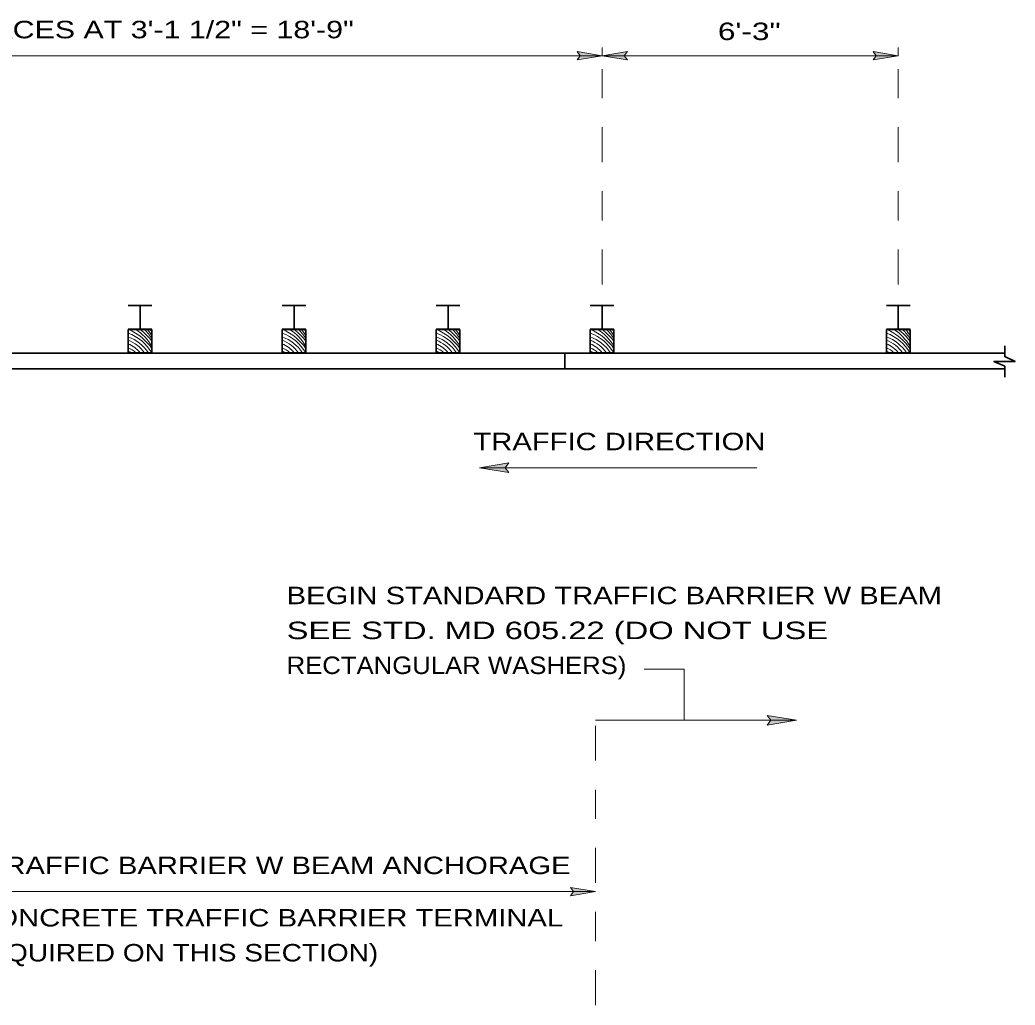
# Model space of a CAD drawing. Extents: x 49.7 to 60, y 209.2 to 216.1.
# Drawn here: x 56.086 to 59.505, y 212.714 to 216.099 of the extents above; entities that cross this region are included whole.
import ezdxf
from ezdxf.enums import TextEntityAlignment as Align

# ---------------------------------------------------------------- set-up
doc = ezdxf.new("R2010")
doc.units = 0
doc.header["$LTSCALE"] = 0.024
doc.linetypes.add('DOT_DASHED', pattern=[7.7, 5, -1.2, 0.3, -1.2])
for name, color, linetype, lineweight in [('1', 7, 'Continuous', 35), ('10', 7, 'Continuous', 13), ('12', 7, 'Continuous', 53), ('6', 7, 'Continuous', 13)]:
    doc.layers.add(name, color=color, linetype=linetype, lineweight=lineweight)

msp = doc.modelspace()

# ---------------------------------------------------------------- hatches: boundary and pattern name
at = {"layer": '10'}
for points in [[(58.08642, 215.97608), (58, 215.9905), (58.01075, 215.97608), (58, 215.96175)], [(58.08642, 215.97608), (58.17283, 215.9905), (58.162, 215.97608), (58.17283, 215.96175)], [(59.10375, 215.97608), (59.01733, 215.9905), (59.02817, 215.97608), (59.01733, 215.96175)], [(57.76608, 214.54375), (57.66525, 214.56058), (57.76608, 214.57733), (57.7535, 214.56058)], [(58.7545, 213.6925), (58.65367, 213.67567), (58.66625, 213.6925), (58.65367, 213.70925)], [(58.06392, 213.10408), (57.9775, 213.08967), (57.98833, 213.10408), (57.9775, 213.11842)]]:
    msp.add_hatch(color=256, dxfattribs=at).paths.add_polyline_path(points)

# ---------------------------------------------------------------- linework, layer by layer
at = {"layer": '1'}
for p, q in [((56.458, 215.11825), (56.5395, 215.11825)), ((56.49867, 215.03692), (56.49867, 215.11825)), ((56.98717, 215.11825), (57.06867, 215.11825)), ((57.02783, 215.03692), (57.02783, 215.11825)), ((57.51633, 215.11825), (57.59775, 215.11825)), ((57.557, 215.03692), (57.557, 215.11825)), ((58.0455, 215.11825), (58.12692, 215.11825)), ((58.08617, 215.03692), (58.08617, 215.11825)), ((59.063, 215.11825), (59.14442, 215.11825)), ((59.10375, 215.03692), (59.10375, 215.11825)), ((56.458, 215.03692), (56.53933, 215.03692)), ((56.458, 215.03558), (56.458, 214.9555)), ((56.458, 215.03558), (56.53933, 215.03558)), ((56.53933, 215.03558), (56.53933, 214.9555)), ((56.98717, 215.03692), (57.0685, 215.03692)), ((56.98717, 215.03558), (56.98717, 214.9555)), ((56.98717, 215.03558), (57.0685, 215.03558)), ((57.0685, 215.03558), (57.0685, 214.9555)), ((57.51633, 215.03692), (57.59767, 215.03692)), ((57.51633, 215.03558), (57.51633, 214.9555)), ((57.51633, 215.03558), (57.59767, 215.03558)), ((57.59767, 215.03558), (57.59767, 214.9555)), ((58.0455, 215.03692), (58.12683, 215.03692)), ((58.0455, 215.03558), (58.0455, 214.9555)), ((58.0455, 215.03558), (58.12683, 215.03558)), ((58.12683, 215.03558), (58.12683, 214.9555)), ((59.063, 215.03692), (59.14442, 215.03692)), ((59.063, 215.03558), (59.063, 214.9555)), ((59.063, 215.03558), (59.14442, 215.03558)), ((59.14442, 215.03558), (59.14442, 214.9555)), ((53.85392, 214.954), (59.47, 214.954)), ((56.458, 214.9555), (56.53933, 214.9555)), ((56.98717, 214.9555), (57.0685, 214.9555)), ((57.51633, 214.9555), (57.59767, 214.9555)), ((57.95833, 214.90025), (57.95833, 214.95458)), ((58.0455, 214.9555), (58.12683, 214.9555)), ((59.063, 214.9555), (59.14442, 214.9555)), ((59.47, 214.89975), (53.72958, 214.89975))]:
    msp.add_line(p, q, dxfattribs=at)
at = {"layer": '10'}
for p, q in [((58, 215.9905), (58.08642, 215.97608)), ((58, 215.9905), (58.01075, 215.97608)), ((58.08642, 215.97608), (58.08642, 216.00492)), ((58.17283, 215.9905), (58.08642, 215.97608)), ((58.17283, 215.9905), (58.162, 215.97608)), ((59.01733, 215.9905), (59.10375, 215.97608)), ((59.01733, 215.9905), (59.02817, 215.97608)), ((59.10375, 215.97608), (59.10375, 216.00492)), ((58.08642, 215.97608), (54.9095, 215.97608)), ((58, 215.96175), (58.08642, 215.97608)), ((58, 215.96175), (58.01075, 215.97608)), ((58.08642, 215.97608), (59.10375, 215.97608)), ((58.17283, 215.96175), (58.08642, 215.97608)), ((58.17283, 215.96175), (58.162, 215.97608)), ((59.01733, 215.96175), (59.10375, 215.97608)), ((59.01733, 215.96175), (59.02817, 215.97608)), ((57.76608, 214.57733), (57.66525, 214.56058)), ((57.66525, 214.56058), (58.61758, 214.56058)), ((57.76608, 214.54375), (57.66525, 214.56058)), ((57.76608, 214.57733), (57.7535, 214.56058)), ((57.76608, 214.54375), (57.7535, 214.56058)), ((58.23025, 213.86825), (58.36817, 213.86825)), ((58.36817, 213.86825), (58.36817, 213.6925)), ((58.65367, 213.70925), (58.7545, 213.6925)), ((58.65367, 213.70925), (58.66625, 213.6925)), ((58.06392, 213.6925), (58.7545, 213.6925)), ((58.65367, 213.67567), (58.7545, 213.6925)), ((58.65367, 213.67567), (58.66625, 213.6925)), ((57.9775, 213.11842), (58.06392, 213.10408)), ((57.9775, 213.11842), (57.98833, 213.10408)), ((53.60783, 213.10408), (58.06392, 213.10408)), ((57.9775, 213.08967), (58.06392, 213.10408)), ((57.9775, 213.08967), (57.98833, 213.10408))]:
    msp.add_line(p, q, dxfattribs=at)
at = {"layer": '10', "linetype": 'DOT_DASHED'}
for p, q in [((58.08642, 215.19025), (58.08642, 216.00492)), ((59.10375, 215.19025), (59.10375, 216.00492)), ((58.06392, 212.71392), (58.06392, 213.72125))]:
    msp.add_line(p, q, dxfattribs=at)
at = {"layer": '10', "lineweight": 35}
for p, q in [((59.47, 214.942), (59.47, 214.97975)), ((59.47, 214.90883), (59.47, 214.87117))]:
    msp.add_line(p, q, dxfattribs=at)
at = {"layer": '10'}
for points in [[(58.08642, 215.97608), (58, 215.9905), (58.01075, 215.97608), (58, 215.96175)], [(58.08642, 215.97608), (58.17283, 215.9905), (58.162, 215.97608), (58.17283, 215.96175)], [(59.10375, 215.97608), (59.01733, 215.9905), (59.02817, 215.97608), (59.01733, 215.96175)], [(57.76608, 214.54375), (57.66525, 214.56058), (57.76608, 214.57733), (57.7535, 214.56058)], [(58.7545, 213.6925), (58.65367, 213.67567), (58.66625, 213.6925), (58.65367, 213.70925)], [(58.06392, 213.10408), (57.9775, 213.08967), (57.98833, 213.10408), (57.9775, 213.11842)]]:
    msp.add_lwpolyline(points, close=True, dxfattribs=at)
at = {"layer": '10', "lineweight": 35}
msp.add_lwpolyline([(59.46958, 214.90892), (59.43242, 214.92517), (59.505, 214.92575), (59.46958, 214.94258)], dxfattribs=at)
at = {"layer": '6'}
for centre, radius, start, end in [((56.38367, 214.86339), 0.18836, 34.17863, 66.11666), ((56.37975, 214.87918), 0.18798, 31.80949, 56.32878), ((56.38588, 214.8853), 0.18798, 35.19443, 53.09813), ((56.38168, 214.90169), 0.18798, 32.90846, 45.43912), ((56.38168, 214.91219), 0.18798, 32.90846, 41.04364), ((56.37706, 214.93151), 0.18798, 30.21852, 33.63016), ((56.91279, 214.86339), 0.18836, 34.17863, 66.11666), ((56.90887, 214.87918), 0.18798, 31.80949, 56.32878), ((56.915, 214.8853), 0.18798, 35.19443, 53.09813), ((56.9108, 214.90169), 0.18798, 32.90846, 45.43912), ((56.9108, 214.91219), 0.18798, 32.90846, 41.04364), ((56.90618, 214.93151), 0.18798, 30.21852, 33.63016), ((57.44192, 214.86339), 0.18836, 34.17863, 66.11666), ((57.438, 214.87918), 0.18798, 31.80949, 56.32878), ((57.44413, 214.8853), 0.18798, 35.19443, 53.09813), ((57.43993, 214.90169), 0.18798, 32.90846, 45.43912), ((57.43993, 214.91219), 0.18798, 32.90846, 41.04364), ((57.43531, 214.93151), 0.18798, 30.21852, 33.63016), ((57.97104, 214.86339), 0.18836, 34.17863, 66.11666), ((57.96712, 214.87918), 0.18798, 31.80949, 56.32878), ((57.97325, 214.8853), 0.18798, 35.19443, 53.09813), ((57.96905, 214.90169), 0.18798, 32.90846, 45.43912), ((57.96905, 214.91219), 0.18798, 32.90846, 41.04364), ((57.96443, 214.93151), 0.18798, 30.21852, 33.63016), ((58.98859, 214.86335), 0.18836, 34.17863, 66.11666), ((58.98467, 214.87914), 0.18798, 31.80949, 56.32878), ((58.9908, 214.88526), 0.18798, 35.19443, 53.09813), ((58.9866, 214.90165), 0.18798, 32.90846, 45.43912), ((58.9866, 214.91215), 0.18798, 32.90846, 41.04364), ((58.98198, 214.93147), 0.18798, 30.21852, 33.63016), ((56.40298, 214.87558), 0.15754, 30.50061, 69.49881), ((56.40262, 214.86913), 0.15183, 34.69089, 68.54375), ((56.41165, 214.88195), 0.12585, 35.78195, 68.31044), ((56.94077, 214.88195), 0.12585, 35.78195, 68.31044), ((56.93211, 214.87558), 0.15754, 30.50061, 69.49881), ((56.93175, 214.86913), 0.15183, 34.69089, 68.54375), ((57.46123, 214.87558), 0.15754, 30.50061, 69.49881), ((57.46087, 214.86913), 0.15183, 34.69089, 68.54375), ((57.4699, 214.88195), 0.12585, 35.78195, 68.31044), ((57.99902, 214.88195), 0.12585, 35.78195, 68.31044), ((57.99036, 214.87558), 0.15754, 30.50061, 69.49881), ((57.99, 214.86913), 0.15183, 34.69089, 68.54375), ((59.01657, 214.88191), 0.12585, 35.78195, 68.31044), ((59.00791, 214.87554), 0.15754, 30.50061, 69.49881), ((59.00755, 214.86909), 0.15183, 34.69089, 68.54375), ((56.42349, 214.89772), 0.09472, 37.61828, 68.52708), ((56.42993, 214.90237), 0.07566, 44.64315, 68.09106), ((56.4353, 214.90978), 0.05615, 54.58973, 65.97576), ((56.95261, 214.89772), 0.09472, 37.61828, 68.52708), ((56.95905, 214.90237), 0.07566, 44.64315, 68.09106), ((56.96443, 214.90978), 0.05615, 54.58973, 65.97576), ((57.48174, 214.89772), 0.09472, 37.61828, 68.52708), ((57.48818, 214.90237), 0.07566, 44.64315, 68.09106), ((57.49355, 214.90978), 0.05615, 54.58973, 65.97576), ((58.01086, 214.89772), 0.09472, 37.61828, 68.52708), ((58.0173, 214.90237), 0.07566, 44.64315, 68.09106), ((58.02268, 214.90978), 0.05615, 54.58973, 65.97576), ((59.02841, 214.89768), 0.09472, 37.61828, 68.52708), ((59.03485, 214.90233), 0.07566, 44.64315, 68.09106), ((59.04022, 214.90974), 0.05615, 54.58973, 65.97576)]:
    msp.add_arc(centre, radius, start, end, dxfattribs=at)

# ---------------------------------------------------------------- texts
at = {"layer": '12'}
for s, width, p in [('6 SPACES AT 3\'-1 1/2" = 18\'-9"', 1.3, (56.49912, 216.036)), ('6\'-3"', 1.35, (58.59171, 216.02992)), ('TRAFFIC DIRECTION', 1.25, (58.14554, 214.6205)), (' 26\'-10 3/4" BASIS OF PAYMENT PER EACH FOR TRAFFIC BARRIER W BEAM ANCHORAGE', 1.25, (55.8155, 213.164)), ('AT PRECAST 32 INCH F SHAPE TEMPORARY CONCRETE TRAFFIC BARRIER TERMINAL', 1.25, (55.84554, 212.984)), ('END (RECTANGULAR WASHERS REQUIRED ON THIS SECTION)', 1.2, (55.84554, 212.86392))]:
    msp.add_text(s, height=0.06001, dxfattribs=dict(at, width=width)).set_placement(p, align=Align.CENTER)
for s, width, p in [('BEGIN STANDARD TRAFFIC BARRIER W BEAM', 1.25, (57.00225, 214.0915)), ('SEE STD. MD 605.22 (DO NOT USE ', 1.4, (57.00225, 213.9715)), ('RECTANGULAR WASHERS)', 1.1, (57.00225, 213.8515))]:
    msp.add_text(s, height=0.06001, dxfattribs=dict(at, width=width)).set_placement(p)

doc.saveas('drawing.dxf')
